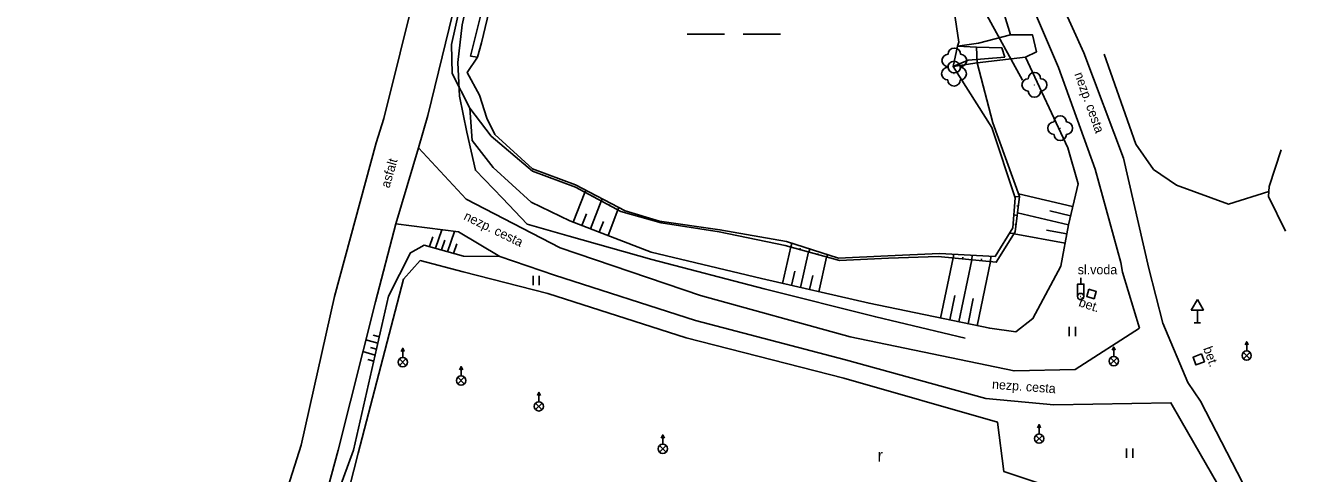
# Model space of a CAD drawing. Extents: x -639360 to -639196, y -1157339 to -1157085.
# Drawn here: x -639360.1 to -639257.9, y -1157191 to -1157154.9 of the extents above; entities that cross this region are included whole.
import ezdxf

# ---------------------------------------------------------------- set-up
doc = ezdxf.new("R2010")
doc.units = 0
for name, color, linetype in [('POMOC_POPIS', 7, 'Continuous'), ('ROZHRANÍ_PLOCH', 7, 'Continuous'), ('VÝŠKOPIS', 7, 'Continuous'), ('ZELEŇ', 7, 'Continuous'), ('ZN_BP', 7, 'Continuous'), ('ZN_DOPLŇKOVÉ', 7, 'Continuous'), ('ZN_KULTUR', 7, 'Continuous')]:
    doc.layers.add(name, color=color, linetype=linetype)

msp = doc.modelspace()

# ---------------------------------------------------------------- linework, layer by layer
at = {"layer": 'ROZHRANÍ_PLOCH'}
for points in [[(-639331.83, -1157164.38), (-639331.19, -1157162.4), (-639327.28, -1157146.63), (-639324.46, -1157132.51), (-639322.54, -1157119.95), (-639322.22, -1157108.89), (-639322.22, -1157101.32), (-639322.43, -1157097.78), (-639322.93, -1157094.85), (-639323.73, -1157091.41)], [(-639328.42, -1157164.76), (-639327.67, -1157162.16), (-639324.21, -1157148.06), (-639321.04, -1157132.66), (-639319.22, -1157120.22), (-639318.09, -1157107.96), (-639317.99, -1157102.89), (-639317.43, -1157100.17)], [(-639295.62, -1157123.87), (-639292.36, -1157127.82), (-639287.21, -1157135.96), (-639281.43, -1157147.61), (-639276.89, -1157158.29), (-639273.94, -1157166.49), (-639271.87, -1157174.02), (-639271.72, -1157174.78), (-639270.37, -1157179.29)], [(-639280.83, -1157129.7), (-639282.8, -1157131.07), (-639283.95, -1157134.49), (-639283.11, -1157139.55), (-639279.4, -1157147.03), (-639274.83, -1157157.12), (-639271.66, -1157165.61), (-639269.62, -1157174.5), (-639268.48, -1157178.89)], [(-639321.84, -1157150.01), (-639323.34, -1157156.32), (-639323.67, -1157157.47), (-639324.49, -1157158.71), (-639323.51, -1157160.53), (-639322.9, -1157162.38), (-639322.27, -1157163.7), (-639319.22, -1157166.46), (-639315.78, -1157167.75), (-639311.76, -1157169.85), (-639309, -1157170.67), (-639304.14, -1157171.37), (-639298.79, -1157172.33), (-639294.6, -1157173.66), (-639290.62, -1157173.46), (-639286.46, -1157173.28), (-639281.98, -1157173.53), (-639280.55, -1157171.22), (-639280.36, -1157168.81), (-639282.25, -1157163.14), (-639285.36, -1157158.23), (-639285.02, -1157156.59), (-639284.91, -1157156.26), (-639285.39, -1157153.02)], [(-639259.94, -1157168.3), (-639263.19, -1157169.3), (-639267.38, -1157167.77), (-639269.22, -1157166.53), (-639270.66, -1157164.47), (-639273.21, -1157157.23)], [(-639331.83, -1157164.38), (-639335.16, -1157176.75), (-639337.86, -1157188.73), (-639341.57, -1157200.42), (-639345.86, -1157215.81), (-639349.27, -1157228.73), (-639352.21, -1157241.42), (-639356.25, -1157254.18), (-639360.06, -1157267.98)], [(-639328.42, -1157164.76), (-639330.23, -1157170.89), (-639331.87, -1157177.18), (-639334.88, -1157189.12), (-639338.37, -1157202.04), (-639342.24, -1157216.44), (-639345.64, -1157229.64), (-639349.1, -1157242.1), (-639352.92, -1157255.44), (-639356.43, -1157269.06)], [(-639270.37, -1157179.29), (-639275.54, -1157182.64), (-639280.45, -1157182.74), (-639293.66, -1157180), (-639305.71, -1157176.68), (-639317, -1157172.84), (-639324.57, -1157168.92), (-639328.42, -1157164.76)], [(-639207.48, -1157338.86), (-639212.63, -1157326.34), (-639217.41, -1157314.31), (-639222.1, -1157302.14), (-639226.58, -1157290.28), (-639230.94, -1157278.76), (-639235.07, -1157267.69), (-639239.22, -1157256.58), (-639243.19, -1157244.58), (-639247.95, -1157233.47), (-639251.01, -1157223.03), (-639255.87, -1157212.42), (-639259.69, -1157201.48), (-639263.03, -1157193.67), (-639267.01, -1157186.76), (-639267.83, -1157185.31), (-639277.25, -1157185.48), (-639282.74, -1157184.98), (-639294.02, -1157181.84), (-639306.1, -1157178.69), (-639317.46, -1157175.03), (-639321.87, -1157173.53), (-639325.2, -1157171.55), (-639330.23, -1157170.89)], [(-639274.44, -1157176.15), (-639273.84, -1157176.35), (-639274.02, -1157176.93), (-639274.61, -1157176.74), (-639274.44, -1157176.15)], [(-639205.68, -1157337.95), (-639210.93, -1157325.66), (-639215.58, -1157313.63), (-639220.66, -1157301.89), (-639224.76, -1157289.56), (-639229.12, -1157277.82), (-639233.13, -1157266.71), (-639238.12, -1157256.22), (-639241.95, -1157244.15), (-639246.22, -1157232.66), (-639249.87, -1157222.73), (-639253.87, -1157211.12), (-639257.99, -1157200.71), (-639261.64, -1157192.58), (-639265.44, -1157185.18), (-639266.46, -1157183.69), (-639268.48, -1157178.89)], [(-639265.36, -1157181.37), (-639265.13, -1157182.01), (-639265.82, -1157182.26), (-639266.05, -1157181.64), (-639265.36, -1157181.37)]]:
    msp.add_lwpolyline(points, dxfattribs=at)
at = {"layer": 'VÝŠKOPIS'}
for p, q in [((-639315.95, -1157170.76), (-639315.02, -1157168.36)), ((-639315.02, -1157168.36), (-639314.93, -1157168.19)), ((-639314.36, -1157168.71), (-639314.32, -1157168.64)), ((-639313.7, -1157169.07), (-639313.6, -1157168.89)), ((-639280.03, -1157168.72), (-639280.4, -1157168.68)), ((-639275.74, -1157169.51), (-639280.1, -1157168.49)), ((-639314.55, -1157171.3), (-639313.69, -1157169.07)), ((-639313.15, -1157171.84), (-639312.36, -1157169.78)), ((-639313.04, -1157169.42), (-639313, -1157169.35)), ((-639312.37, -1157169.77), (-639312.27, -1157169.58)), ((-639280.12, -1157169.47), (-639280.24, -1157169.45)), ((-639275.91, -1157170.24), (-639277.58, -1157169.85)), ((-639315.25, -1157171.03), (-639314.89, -1157170.1)), ((-639313.85, -1157171.57), (-639313.52, -1157170.71)), ((-639280.21, -1157170.21), (-639280.47, -1157170.18)), ((-639280.29, -1157170.96), (-639280.39, -1157170.95)), ((-639276.08, -1157170.97), (-639280.18, -1157170.01)), ((-639327.51, -1157172.73), (-639327.25, -1157171.95)), ((-639327.03, -1157172.86), (-639326.52, -1157171.38)), ((-639326.07, -1157173.14), (-639325.51, -1157171.51)), ((-639280.44, -1157171.68), (-639280.81, -1157171.64)), ((-639276.35, -1157172.44), (-639280.45, -1157171.69)), ((-639276.21, -1157171.71), (-639277.84, -1157171.41)), ((-639326.55, -1157173), (-639326.28, -1157172.22)), ((-639325.59, -1157173.28), (-639325.32, -1157172.5)), ((-639299.11, -1157175.69), (-639298.44, -1157172.76)), ((-639298.42, -1157172.76), (-639298.34, -1157172.47)), ((-639297.7, -1157172.96), (-639297.67, -1157172.86)), ((-639296.98, -1157173.17), (-639296.91, -1157172.93)), ((-639297.65, -1157176.03), (-639297, -1157173.16)), ((-639296.26, -1157173.37), (-639296.23, -1157173.28)), ((-639296.19, -1157176.36), (-639295.55, -1157173.57)), ((-639295.54, -1157173.57), (-639295.48, -1157173.38)), ((-639286.37, -1157178.49), (-639285.36, -1157173.64)), ((-639285.35, -1157173.64), (-639285.32, -1157173.34)), ((-639284.9, -1157178.79), (-639283.86, -1157173.79)), ((-639284.6, -1157173.72), (-639284.59, -1157173.59)), ((-639283.86, -1157173.79), (-639283.82, -1157173.43)), ((-639283.43, -1157179.1), (-639282.36, -1157173.94)), ((-639283.11, -1157173.87), (-639283.09, -1157173.71)), ((-639282.36, -1157173.94), (-639282.32, -1157173.51)), ((-639298.38, -1157175.86), (-639298.12, -1157174.7)), ((-639296.92, -1157176.19), (-639296.66, -1157175.06)), ((-639285.63, -1157178.64), (-639285.22, -1157176.67)), ((-639284.16, -1157178.95), (-639283.74, -1157176.92)), ((-639331.56, -1157180.01), (-639332.05, -1157179.87)), ((-639331.67, -1157180.5), (-639332.64, -1157180.23)), ((-639331.78, -1157180.99), (-639332.27, -1157180.85)), ((-639331.9, -1157181.47), (-639332.88, -1157181.19)), ((-639332.01, -1157181.96), (-639332.49, -1157181.82))]:
    msp.add_line(p, q, dxfattribs=at)
for points in [[(-639281.72, -1157152.47), (-639280.74, -1157155.68), (-639278.98, -1157155.66), (-639278.66, -1157157.05), (-639279.55, -1157157.47), (-639276.12, -1157164.78), (-639275.31, -1157167.68), (-639276.08, -1157170.98), (-639276.69, -1157174.3), (-639278.94, -1157178.53), (-639280.31, -1157179.59), (-639282.42, -1157179.31), (-639292.13, -1157177.29), (-639300.79, -1157175.31), (-639309.68, -1157173.17), (-639316.23, -1157170.65), (-639319.35, -1157169.16), (-639322.39, -1157166.35), (-639324.1, -1157164.19), (-639324.27, -1157161.58), (-639325.7, -1157158.79), (-639325.75, -1157156.44), (-639325.12, -1157153.58)], [(-639285.02, -1157156.59), (-639283.31, -1157156.35), (-639280.74, -1157155.68)], [(-639285.02, -1157156.59), (-639283.49, -1157156.66), (-639281.43, -1157156.72), (-639281.19, -1157157.46)], [(-639285.36, -1157158.23), (-639284.15, -1157157.71), (-639281.19, -1157157.46)], [(-639285.36, -1157158.23), (-639283.42, -1157157.92), (-639279.55, -1157157.47)], [(-639283.42, -1157157.92), (-639283.49, -1157156.66)], [(-639324.27, -1157161.58), (-639322.56, -1157163.82), (-639319.22, -1157166.66), (-639315.78, -1157167.95), (-639312.12, -1157169.91), (-639308.88, -1157170.81), (-639304.2, -1157171.55), (-639298.89, -1157172.63), (-639294.51, -1157173.86), (-639290.58, -1157173.65), (-639286.58, -1157173.52), (-639281.89, -1157173.99), (-639280.36, -1157171.55), (-639280.03, -1157168.69), (-639282.18, -1157162.76), (-639283.42, -1157157.92)], [(-639321.87, -1157173.53), (-639324.78, -1157173.51), (-639327.96, -1157172.6), (-639329.05, -1157173.23), (-639330.82, -1157176.73), (-639333.63, -1157189.13), (-639338.37, -1157202.04)]]:
    msp.add_lwpolyline(points, dxfattribs=at)
at = {"layer": 'ZELEŇ'}
msp.add_lwpolyline([(-639263.89, -1157195.54), (-639272.49, -1157193.78), (-639281.29, -1157190.84), (-639281.78, -1157186.88), (-639294.17, -1157183.32), (-639306.87, -1157180.07), (-639317.99, -1157176.5), (-639324.82, -1157174.77), (-639328.28, -1157173.85), (-639329.62, -1157175.35), (-639333.27, -1157189.37), (-639336.7, -1157202.86), (-639340.39, -1157216.72), (-639344.16, -1157230.08), (-639347.28, -1157242.28), (-639351.74, -1157255.63), (-639355.24, -1157269.24)], dxfattribs=at)
for centre in [(-639285.27, -1157157.73), (-639285.29, -1157158.8), (-639278.82, -1157159.7), (-639276.74, -1157163.19)]:
    msp.add_circle(centre, 0.0005, dxfattribs=at)
for centre, start, end in [((-639285.77, -1157157.73), 90, 270), ((-639285.27, -1157157.23), 0, 180), ((-639284.77, -1157157.73), 270, 90), ((-639285.79, -1157158.8), 90, 270), ((-639285.29, -1157158.3), 0, 180), ((-639285.27, -1157158.23), 180, 360), ((-639284.79, -1157158.8), 270, 90), ((-639285.29, -1157159.3), 180, 360), ((-639279.32, -1157159.7), 90, 270), ((-639278.82, -1157159.2), 0, 180), ((-639278.32, -1157159.7), 270, 90), ((-639278.82, -1157160.2), 180, 360), ((-639277.24, -1157163.19), 90, 270), ((-639276.74, -1157162.69), 0, 180), ((-639276.24, -1157163.19), 270, 90), ((-639276.74, -1157163.69), 180, 360)]:
    msp.add_arc(centre, 0.5, start, end, dxfattribs=at)
at = {"layer": 'ZN_BP'}
for p, q in [((-639329.68, -1157181.67), (-639329.68, -1157180.92)), ((-639272.43, -1157181.57), (-639272.43, -1157180.82)), ((-639261.73, -1157181.14), (-639261.73, -1157180.39)), ((-639329.95, -1157182.3), (-639329.42, -1157181.78)), ((-639329.42, -1157182.31), (-639329.95, -1157181.78)), ((-639272.7, -1157182.21), (-639272.17, -1157181.69)), ((-639272.17, -1157182.22), (-639272.7, -1157181.69)), ((-639261.99, -1157181.77), (-639261.47, -1157181.25)), ((-639261.47, -1157181.78), (-639261.99, -1157181.25)), ((-639324.98, -1157183.15), (-639324.98, -1157182.4)), ((-639325.24, -1157183.78), (-639324.72, -1157183.26)), ((-639324.72, -1157183.79), (-639325.24, -1157183.26)), ((-639318.72, -1157185.23), (-639318.72, -1157184.48)), ((-639318.98, -1157185.86), (-639318.46, -1157185.34)), ((-639318.46, -1157185.87), (-639318.98, -1157185.34)), ((-639278.44, -1157187.82), (-639278.44, -1157187.07)), ((-639308.74, -1157188.65), (-639308.74, -1157187.9)), ((-639278.7, -1157188.46), (-639278.18, -1157187.94)), ((-639278.18, -1157188.47), (-639278.7, -1157187.94)), ((-639309.01, -1157189.28), (-639308.48, -1157188.76)), ((-639308.48, -1157189.29), (-639309.01, -1157188.76))]:
    msp.add_line(p, q, dxfattribs=at)
for points in [[(-639329.81, -1157181.17), (-639329.68, -1157180.92), (-639329.56, -1157181.17)], [(-639272.56, -1157181.07), (-639272.43, -1157180.82), (-639272.31, -1157181.07)], [(-639261.85, -1157180.64), (-639261.73, -1157180.39), (-639261.6, -1157180.64)], [(-639325.1, -1157182.65), (-639324.98, -1157182.4), (-639324.85, -1157182.65)], [(-639318.84, -1157184.73), (-639318.72, -1157184.48), (-639318.59, -1157184.73)], [(-639278.57, -1157187.32), (-639278.44, -1157187.07), (-639278.32, -1157187.32)], [(-639308.86, -1157188.15), (-639308.74, -1157187.9), (-639308.61, -1157188.15)]]:
    msp.add_lwpolyline(points, dxfattribs=at)
for centre in [(-639261.73, -1157181.51), (-639329.68, -1157182.04), (-639272.43, -1157181.95), (-639324.98, -1157183.52), (-639318.72, -1157185.6), (-639278.44, -1157188.2), (-639308.74, -1157189.02)]:
    msp.add_circle(centre, 0.375, dxfattribs=at)
at = {"layer": 'ZN_DOPLŇKOVÉ'}
for p, q in [((-639275.09, -1157175.75), (-639275.09, -1157175.25)), ((-639265.7, -1157176.99), (-639266.2, -1157177.86)), ((-639265.7, -1157176.99), (-639265.2, -1157177.86)), ((-639266.2, -1157177.86), (-639265.2, -1157177.86)), ((-639265.7, -1157178.86), (-639265.7, -1157177.86)), ((-639265.95, -1157178.86), (-639265.45, -1157178.86))]:
    msp.add_line(p, q, dxfattribs=at)
for points in [[(-639310.11, -1157115.69), (-639304.34, -1157114.33), (-639299.54, -1157123.45), (-639294.36, -1157132.63), (-639287.14, -1157146.23), (-639285.54, -1157148.86), (-639284.14, -1157151.38), (-639279.78, -1157159.32)], [(-639323.67, -1157157.47), (-639324.22, -1157157.38), (-639321.86, -1157147.91), (-639320.11, -1157141.12), (-639318.09, -1157133.67), (-639315.13, -1157123.01), (-639314.38, -1157123.19)], [(-639284.4, -1157180.11), (-639291.6, -1157178.4), (-639300.57, -1157176.13), (-639309.61, -1157173.78), (-639316.28, -1157171.9), (-639319.67, -1157170.92), (-639321.65, -1157168.83), (-639323.82, -1157166.58), (-639324.52, -1157163.52), (-639325.11, -1157160.62), (-639325.24, -1157157.89), (-639324.88, -1157154.86), (-639324.21, -1157151.79), (-639322.63, -1157145.95), (-639321.31, -1157140.99)], [(-639258.94, -1157164.94), (-639259.91, -1157167.9), (-639259.96, -1157168.68), (-639258.6, -1157171.48)], [(-639275.34, -1157176.75), (-639275.34, -1157175.75), (-639274.84, -1157175.75), (-639274.84, -1157176.75)]]:
    msp.add_lwpolyline(points, dxfattribs=at)
for radius in [0.25, 0.005]:
    msp.add_circle((-639275.09, -1157176.75), radius, dxfattribs=at)
at = {"layer": 'ZN_KULTUR'}
for p, q in [((-639306.77, -1157155.61), (-639303.77, -1157155.61)), ((-639302.27, -1157155.61), (-639299.27, -1157155.61)), ((-639319.19, -1157175.84), (-639319.19, -1157175.09)), ((-639318.69, -1157175.84), (-639318.69, -1157175.09)), ((-639276.02, -1157179.94), (-639276.02, -1157179.19)), ((-639275.52, -1157179.94), (-639275.52, -1157179.19)), ((-639271.4, -1157189.74), (-639271.4, -1157188.99)), ((-639270.9, -1157189.74), (-639270.9, -1157188.99))]:
    msp.add_line(p, q, dxfattribs=at)

# ---------------------------------------------------------------- texts
at = {"layer": 'POMOC_POPIS'}
for s, rotation, p in [('nezp. cesta', 289.7865, (-639275.61, -1157158.83)), ('asfalt', 74.0401, (-639330.75, -1157168.06)), ('nezp. cesta', 334.0553, (-639324.83, -1157170.52)), ('bet.', 341.5651, (-639275.31, -1157177.51)), ('bet.', 289.7672, (-639265.24, -1157180.93)), ('nezp. cesta', 355.9187, (-639282.25, -1157184.18))]:
    msp.add_text(s, height=0.75, rotation=rotation, dxfattribs=at).set_placement(p)
msp.add_text('sl.voda', height=0.75, dxfattribs=at).set_placement((-639275.33, -1157174.96))
at = {"layer": 'ZN_KULTUR'}
msp.add_text('r', height=1, dxfattribs=at).set_placement((-639291.45, -1157190.05))

doc.saveas('drawing.dxf')
